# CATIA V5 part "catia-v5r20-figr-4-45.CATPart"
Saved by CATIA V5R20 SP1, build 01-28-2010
Part number: Part1
Bounding box of the stored display mesh (mm): x -89.975 to 89.975, y -89.975 to 89.975, z 0 to 190
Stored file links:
  D:\v5_r20\psrt_files_downloaded\c04catia-v5r20-prt\catia-v5r20-figr-4-45.CATPart
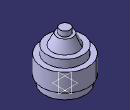
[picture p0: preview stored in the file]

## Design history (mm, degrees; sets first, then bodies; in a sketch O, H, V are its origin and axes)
Set1
  Line1 "Y Axis": stored without definition
  Line2 "Y Axis": stored without definition
  Line3 "X Axis": stored without definition
  Line4 "Z Axis": stored without definition
Body1 (main body)
  Sketch1 on yz-plane, origin (0, 0, 0), H (0, 1, 0), V (0, 0, 1)
    line L1 (0, 0) -> (80, 0)
    line L2 (80, 0) -> (80, 30)
    line L3 (80, 30) -> (90, 30)
    line L4 (90, 30) -> (90, 100)
    line L5 (90, 100) -> (70, 100)
    line L6 (70, 100) -> (70, 130)
    line L7 (70, 130) -> (50, 130)
    line L8 (50, 130) -> (30, 170)
    line L9 (30, 170) -> (20, 170)
    line L10 (20, 170) -> (20, 190)
    line L11 (20, 190) -> (0, 190)
    point P11 (0, 190)
    line L12 (0, 190) -> (0, 0)
    axis line L13 (0, -40) -> (0, 230)
    point P12 (0, -40)
    point P13 (0, 230)
    horizontal: L1 H, L3 H, L5 H, L7 H, L9 H, L11 H
    vertical: L2 V, L4 V, L6 V, L10 V, L12 V, L13 V
    coincidence: P11 V, P12 V, P13 L8
  Shaft1: profile Sketch1, axis Sketch1.L13, angle 360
